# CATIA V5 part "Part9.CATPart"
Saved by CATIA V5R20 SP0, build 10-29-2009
Part number: 3JT9.5X2X13.5
Revision: ANY
Definition: UNKNOWN
Nomenclature: 3JT9.5X2X13.5
Source: Unknown
Bounding box of the stored display mesh (mm): x -6.581 to 6.581, y -1 to 1, z -6.75 to 6.75
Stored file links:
  C:\Users\Utente\Desktop\IO LAVORO\3D X SITO CF\CUMSA\3D files PW\pw081030\pw081030_injection\Part9.CATPart
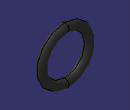
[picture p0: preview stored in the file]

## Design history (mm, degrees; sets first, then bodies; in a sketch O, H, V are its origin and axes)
Body1 "Revolución1" (main body)
  Solid1: solid without history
